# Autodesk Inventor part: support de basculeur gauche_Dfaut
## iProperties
Created: 2006-03
Part Number: support de basculeur gauche_Dfaut
Document SubType Name: Modeling
Designer: Flavien MARTY
Author: Flavien MARTY
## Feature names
1. Base1
